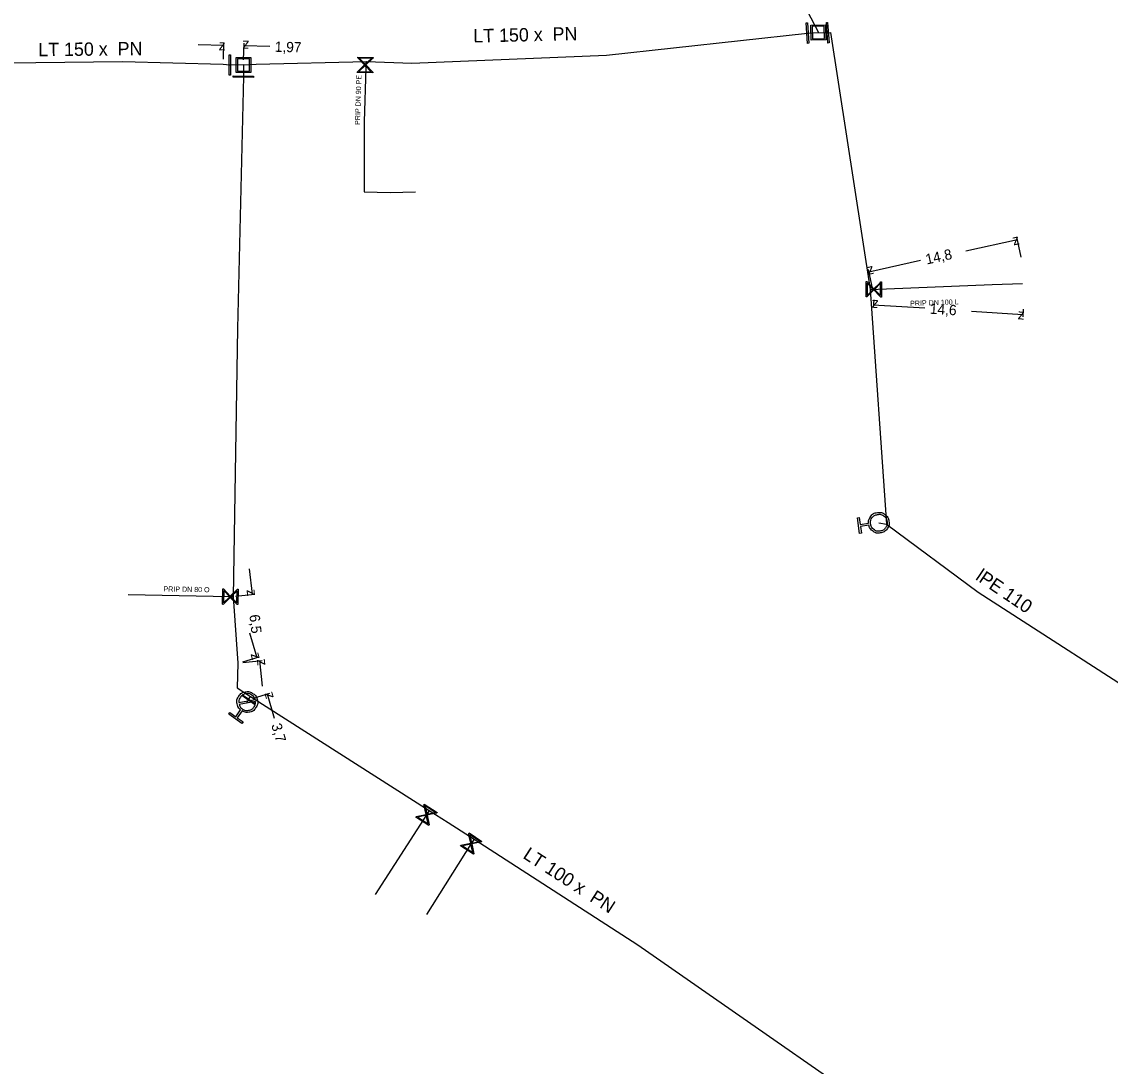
# Model space of a CAD drawing. Extents: x -643842 to -636370, y -1119190 to -1110210.
# Drawn here: x -641892.9 to -641786.8, y -1115563.3 to -1115461.6 of the extents above; entities that cross this region are included whole.
import ezdxf

# ---------------------------------------------------------------- set-up
doc = ezdxf.new("R2010")
doc.units = 0
for name, color, linetype in [('22', 7, 'Continuous'), ('Default', 7, 'Continuous'), ('Level 10', 7, 'Continuous'), ('Level 16', 7, 'Continuous'), ('Level 18', 7, 'Continuous'), ('Level 20', 7, 'Continuous'), ('Level 21', 7, 'Continuous'), ('Level 23', 7, 'Continuous'), ('Level 33', 7, 'Continuous')]:
    doc.layers.add(name, color=color, linetype=linetype)

msp = doc.modelspace()

# ---------------------------------------------------------------- linework, layer by layer
at = {"layer": 'Default'}
for points in [[(-641810.39, -1115510.4), (-641810.41, -1115510.04), (-641810.19, -1115509.75), (-641809.94, -1115509.42), (-641809.53, -1115509.36), (-641809.12, -1115509.3), (-641808.79, -1115509.55), (-641808.46, -1115509.8), (-641808.4, -1115510.21), (-641808.34, -1115510.62), (-641808.59, -1115510.95), (-641808.84, -1115511.28), (-641809.25, -1115511.34), (-641809.66, -1115511.4), (-641809.99, -1115511.15), (-641810.28, -1115510.93), (-641810.36, -1115510.58)], [(-641810.2, -1115510.47), (-641810.15, -1115510.8), (-641809.88, -1115511), (-641809.61, -1115511.2), (-641809.28, -1115511.16), (-641808.94, -1115511.11), (-641808.74, -1115510.84), (-641808.54, -1115510.57), (-641808.59, -1115510.24), (-641808.64, -1115509.9), (-641808.9, -1115509.7), (-641809.17, -1115509.5), (-641809.51, -1115509.55), (-641809.84, -1115509.6), (-641810.04, -1115509.86), (-641810.24, -1115510.13), (-641810.2, -1115510.47)], [(-641871.56, -1115528.57), (-641871.84, -1115528.34), (-641871.9, -1115527.98), (-641871.97, -1115527.57), (-641871.72, -1115527.23), (-641871.49, -1115526.89), (-641871.08, -1115526.82), (-641870.67, -1115526.75), (-641870.33, -1115527), (-641869.99, -1115527.23), (-641869.92, -1115527.64), (-641869.85, -1115528.05), (-641870.09, -1115528.39), (-641870.33, -1115528.73), (-641870.74, -1115528.8), (-641871.1, -1115528.86), (-641871.41, -1115528.68)], [(-641870.13, -1115527.58), (-641870.2, -1115527.32), (-641870.44, -1115527.15), (-641870.71, -1115526.96), (-641871.05, -1115527.01), (-641871.38, -1115527.07), (-641871.57, -1115527.34), (-641871.74, -1115527.58), (-641871.72, -1115527.86)], [(-641871.69, -1115528.04), (-641871.62, -1115528.31), (-641871.38, -1115528.48), (-641871.1, -1115528.67), (-641870.77, -1115528.61), (-641870.44, -1115528.56), (-641870.25, -1115528.28), (-641870.08, -1115528.04), (-641870.1, -1115527.76)]]:
    msp.add_open_spline(points, degree=3, dxfattribs=at)
at = {"layer": 'Level 10'}
for points in [[(-641873.23, -1115465.21), (-641873.18, -1115463.6)], [(-641875.69, -1115463.78), (-641873.19, -1115463.85)], [(-641871.26, -1115465.26), (-641871.21, -1115463.65)], [(-641868.72, -1115463.96), (-641871.22, -1115463.9)], [(-641795.51, -1115484.47), (-641795.94, -1115482.51)], [(-641800.92, -1115483.86), (-641795.89, -1115482.75)], [(-641809.97, -1115487.65), (-641810.4, -1115485.68)], [(-641805.32, -1115484.82), (-641810.35, -1115485.93)], [(-641809.89, -1115488.63), (-641809.94, -1115489.4)], [(-641804.91, -1115489.46), (-641809.93, -1115489.15)], [(-641800.37, -1115489.75), (-641795.35, -1115490.06)], [(-641795.32, -1115489.54), (-641795.37, -1115490.31)], [(-641870.71, -1115514.83), (-641870.43, -1115517.32)], [(-641872.06, -1115517.5), (-641870.18, -1115517.29)], [(-641870.68, -1115521.08), (-641869.98, -1115523.48)], [(-641871.35, -1115523.88), (-641869.74, -1115523.41)], [(-641871.33, -1115523.96), (-641869.45, -1115523.75)], [(-641869.41, -1115526.26), (-641869.69, -1115523.78)], [(-641870.31, -1115527.43), (-641868.7, -1115526.96)], [(-641868.24, -1115529.43), (-641868.94, -1115527.03)]]:
    msp.add_lwpolyline(points, dxfattribs=at)
at = {"layer": 'Level 16'}
for points in [[(-641816.32, -1115461.66), (-641816.21, -1115463.65), (-641816.33, -1115463.66), (-641816.45, -1115461.66), (-641816.32, -1115461.66)], [(-641814.38, -1115461.63), (-641814.23, -1115463.62), (-641814.35, -1115463.63), (-641814.5, -1115461.64), (-641814.38, -1115461.63)], [(-641872.55, -1115464.77), (-641872.54, -1115466.77), (-641872.66, -1115466.77), (-641872.68, -1115464.77), (-641872.55, -1115464.77)], [(-641860.15, -1115464.99), (-641858.65, -1115465.03), (-641858.65, -1115465.09), (-641858.75, -1115465.18), (-641859.36, -1115465.76), (-641858.68, -1115466.46), (-641858.69, -1115466.53), (-641860.19, -1115466.49), (-641860.18, -1115466.43), (-641859.48, -1115465.76), (-641860.06, -1115465.15), (-641860.15, -1115465.06), (-641860.15, -1115464.99)], [(-641860, -1115465.09), (-641859.42, -1115465.7), (-641858.81, -1115465.12), (-641860, -1115465.09)], [(-641858.84, -1115466.43), (-641859.42, -1115465.82), (-641860.03, -1115466.4), (-641858.84, -1115466.43)], [(-641870.29, -1115466.98), (-641872.29, -1115466.94), (-641872.29, -1115466.81), (-641870.29, -1115466.85), (-641870.29, -1115466.98)], [(-641809.12, -1115486.88), (-641809.13, -1115488.38), (-641809.19, -1115488.37), (-641809.28, -1115488.28), (-641809.87, -1115487.68), (-641810.56, -1115488.36), (-641810.63, -1115488.36), (-641810.62, -1115486.86), (-641810.55, -1115486.86), (-641809.87, -1115487.56), (-641809.27, -1115486.97), (-641809.18, -1115486.87), (-641809.12, -1115486.88)], [(-641810.53, -1115488.21), (-641809.93, -1115487.62), (-641810.52, -1115487.02), (-641810.53, -1115488.21)], [(-641809.21, -1115487.03), (-641809.81, -1115487.62), (-641809.22, -1115488.22), (-641809.21, -1115487.03)], [(-641871.8, -1115516.82), (-641871.82, -1115518.32), (-641871.89, -1115518.32), (-641871.98, -1115518.23), (-641872.56, -1115517.62), (-641873.26, -1115518.3), (-641873.32, -1115518.29), (-641873.29, -1115516.8), (-641873.23, -1115516.8), (-641872.56, -1115517.5), (-641871.95, -1115516.92), (-641871.86, -1115516.82), (-641871.8, -1115516.82)], [(-641873.23, -1115518.14), (-641872.62, -1115517.56), (-641873.2, -1115516.95), (-641873.23, -1115518.14)], [(-641871.89, -1115516.98), (-641872.5, -1115517.56), (-641871.92, -1115518.16), (-641871.89, -1115516.98)], [(-641871.38, -1115527.1), (-641870.15, -1115527.97), (-641870.21, -1115528.04), (-641871.43, -1115527.17), (-641871.38, -1115527.1)], [(-641853.66, -1115537.75), (-641852.4, -1115538.57), (-641852.44, -1115538.62), (-641852.56, -1115538.65), (-641853.39, -1115538.82), (-641853.18, -1115539.77), (-641853.22, -1115539.83), (-641854.48, -1115539.01), (-641854.44, -1115538.96), (-641853.49, -1115538.76), (-641853.67, -1115537.93), (-641853.7, -1115537.81), (-641853.66, -1115537.75)], [(-641853.3, -1115539.67), (-641853.47, -1115538.84), (-641854.29, -1115539.02), (-641853.3, -1115539.67)], [(-641853.58, -1115537.92), (-641853.4, -1115538.74), (-641852.59, -1115538.56), (-641853.58, -1115537.92)], [(-641849.3, -1115540.56), (-641848.05, -1115541.38), (-641848.09, -1115541.44), (-641848.21, -1115541.46), (-641849.04, -1115541.63), (-641848.84, -1115542.58), (-641848.87, -1115542.64), (-641850.13, -1115541.81), (-641850.09, -1115541.76), (-641849.14, -1115541.56), (-641849.31, -1115540.74), (-641849.34, -1115540.62), (-641849.3, -1115540.56)], [(-641849.22, -1115540.73), (-641849.05, -1115541.55), (-641848.23, -1115541.38), (-641849.22, -1115540.73)], [(-641848.95, -1115542.48), (-641849.12, -1115541.65), (-641849.95, -1115541.82), (-641848.95, -1115542.48)]]:
    msp.add_lwpolyline(points, dxfattribs=at)
at = {"layer": 'Level 18'}
for points in [[(-641814.59, -1115461.86), (-641814.56, -1115463.31), (-641815.97, -1115463.34), (-641816, -1115461.89), (-641814.59, -1115461.86)], [(-641815.88, -1115462.01), (-641815.85, -1115463.22), (-641814.68, -1115463.19), (-641814.71, -1115461.99), (-641815.88, -1115462.01)], [(-641870.56, -1115465.04), (-641870.56, -1115466.49), (-641871.98, -1115466.49), (-641871.98, -1115465.04), (-641870.56, -1115465.04)], [(-641871.86, -1115465.16), (-641871.86, -1115466.37), (-641870.68, -1115466.37), (-641870.68, -1115465.16), (-641871.86, -1115465.16)]]:
    msp.add_lwpolyline(points, dxfattribs=at)
at = {"layer": 'Level 21'}
for points in [[(-641817.81, -1115449.58), (-641816.79, -1115456.8), (-641816.61, -1115458.45), (-641816.36, -1115460.48), (-641815.28, -1115462.6)], [(-641871.27, -1115465.76), (-641870.03, -1115465.69), (-641859.3, -1115465.44), (-641854.88, -1115465.6), (-641835.9, -1115464.81), (-641816.33, -1115462.66), (-641815.28, -1115462.6)], [(-641815.28, -1115462.6), (-641814.37, -1115462.63), (-641814.11, -1115462.59), (-641810.24, -1115487.62), (-641810.24, -1115487.62), (-641808.63, -1115510.48), (-641799.72, -1115517.12), (-641781.18, -1115529.05), (-641778.14, -1115530.97)], [(-641871.27, -1115465.76), (-641872.61, -1115465.77), (-641873.24, -1115465.71), (-641883.07, -1115465.45), (-641899.98, -1115465.64), (-641901.75, -1115465.65), (-641901.66, -1115491.08), (-641902.17, -1115518.23), (-641902.37, -1115523.29), (-641902.42, -1115523.83)], [(-641871.27, -1115465.76), (-641871.29, -1115466.89), (-641871.86, -1115491.42), (-641872.29, -1115517.56), (-641871.83, -1115524.02), (-641871.88, -1115526.43), (-641870.59, -1115527.26), (-641853.18, -1115538.38), (-641851.35, -1115539.55), (-641848.82, -1115541.18), (-641832.86, -1115551.46), (-641801.98, -1115572.94), (-641783.08, -1115585.41), (-641775.63, -1115590.24)]]:
    msp.add_lwpolyline(points, dxfattribs=at)
at = {"layer": 'Level 23'}
for points in [[(-641859.3, -1115465.44), (-641859.42, -1115465.76), (-641859.37, -1115466.05), (-641859.53, -1115471.3), (-641859.52, -1115478.11), (-641857, -1115478.19), (-641854.52, -1115478.11)], [(-641810.24, -1115487.62), (-641798.35, -1115487.15), (-641795.39, -1115487.04)], [(-641809.39, -1115510.35), (-641808.63, -1115510.48)], [(-641872.29, -1115517.56), (-641872.56, -1115517.56), (-641882.52, -1115517.38)], [(-641870.91, -1115527.81), (-641870.79, -1115527.57), (-641870.59, -1115527.26)], [(-641853.18, -1115538.38), (-641853.44, -1115538.79), (-641858.45, -1115546.57)], [(-641848.82, -1115541.18), (-641849.09, -1115541.6), (-641853.44, -1115548.49)]]:
    msp.add_lwpolyline(points, dxfattribs=at)
at = {"layer": 'Level 33'}
for points in [[(-641810.36, -1115510.58), (-641811.17, -1115510.7), (-641811.08, -1115511.38), (-641811.26, -1115511.41), (-641811.48, -1115509.86), (-641811.3, -1115509.83), (-641811.2, -1115510.52), (-641810.39, -1115510.4)], [(-641871.72, -1115527.86), (-641870.13, -1115527.58)], [(-641870.1, -1115527.76), (-641871.69, -1115528.04)], [(-641871.41, -1115528.68), (-641871.88, -1115529.35), (-641871.32, -1115529.74), (-641871.43, -1115529.89), (-641872.7, -1115528.99), (-641872.6, -1115528.84), (-641872.03, -1115529.24), (-641871.56, -1115528.57)]]:
    msp.add_lwpolyline(points, dxfattribs=at)

# ---------------------------------------------------------------- texts
at = {"layer": '22'}
for s, rotation, p in [('PRIP DN 90 PE', 88.2544, (-641859.93, -1115471.61)), ('PRIP DN 100 L', 1.9713, (-641806.33, -1115489.24)), ('PRIP DN 80 O', 358.9818, (-641879.07, -1115517.04))]:
    msp.add_text(s, height=0.5, rotation=rotation, dxfattribs=at).set_placement(p)
at = {"layer": 'Level 10'}
for s, rotation, p in [('z', 358.4995, (-641873.7, -1115464.33)), ('z', 178.4995, (-641870.71, -1115463.41)), ('1,97', 358.4995, (-641868.24, -1115464.48)), ('z', 12.3799, (-641796.27, -1115483.35)), ('14,8', 12.3799, (-641804.72, -1115485.2)), ('z', 192.3799, (-641809.97, -1115485.33)), ('z', 176.4423, (-641809.4, -1115488.68)), ('14,6', 356.4423, (-641804.44, -1115489.99)), ('z', 356.4423, (-641795.88, -1115490.53)), ('z', 276.4558, (-641870.98, -1115516.88)), ('6,5', 276.4558, (-641870.7, -1115519.34)), ('z', 286.3049, (-641870.6, -1115523.14)), ('z', 96.4558, (-641869.14, -1115524.22)), ('z', 106.3049, (-641868.32, -1115527.37)), ('3,7', 286.3049, (-641868.58, -1115530.05))]:
    msp.add_text(s, height=1, rotation=rotation, dxfattribs=at).set_placement(p)
at = {"layer": 'Level 20'}
for s, rotation, p in [('LT 150 x  PN ', 1.2686, (-641848.88, -1115463.58)), ('LT 150 x  PN ', 0.626, (-641891.26, -1115464.92)), ('lPE 110', 325.9249, (-641800.05, -1115515.83)), ('LT 100 x  PN ', 327.2156, (-641844.14, -1115542.96))]:
    msp.add_text(s, height=1.3, rotation=rotation, dxfattribs=at).set_placement(p)

doc.saveas('drawing.dxf')
